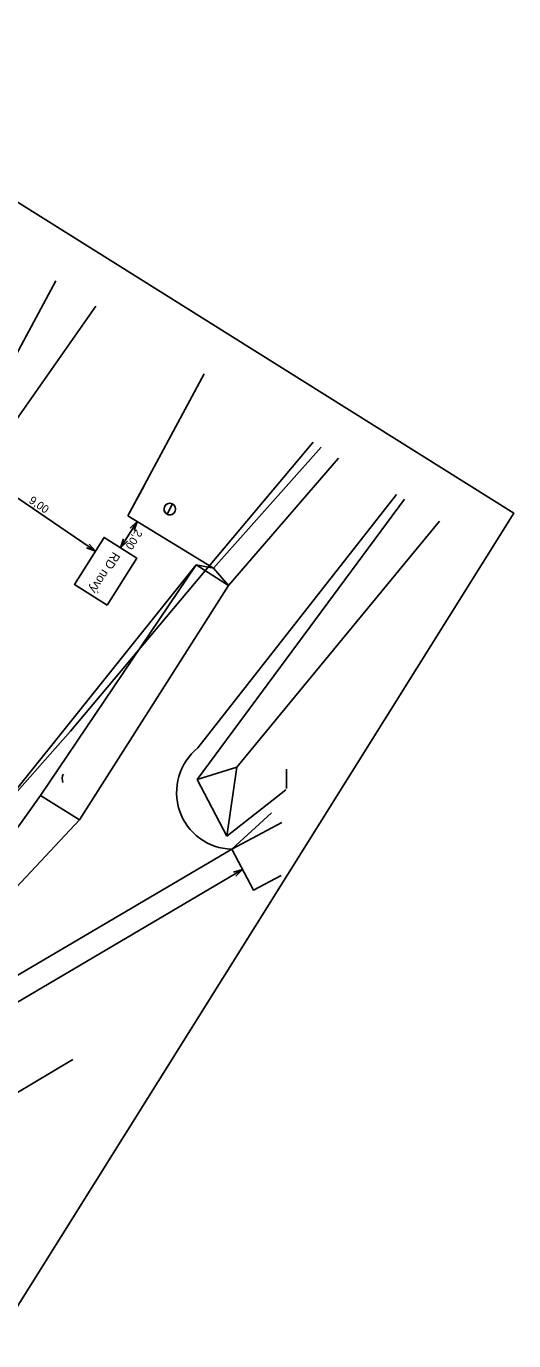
# Model space of a CAD drawing. Extents: x -794960 to -794828, y -1135115 to -1134953.
# Drawn here: x -794859.2 to -794827.6, y -1135038 to -1134952.8 of the extents above; entities that cross this region are included whole.
import ezdxf

# ---------------------------------------------------------------- set-up
doc = ezdxf.new("R2010")
doc.units = 0
for name, color, linetype in [('Implicitní', 7, 'Continuous'), ('Schéma', 7, 'Continuous'), ('Stsitu', 7, 'Continuous'), ('Stsitu - koleje', 7, 'Continuous'), ('Vrstva 1', 7, 'Continuous'), ('Vzor', 7, 'Continuous')]:
    doc.layers.add(name, color=color, linetype=linetype)

msp = doc.modelspace()

# ---------------------------------------------------------------- linework, layer by layer
at = {"layer": 'Implicitní'}
for p, q in [((-794862.154, -1134981.748), (-794854.692, -1134986.84)), ((-794851.996, -1134984.913), (-794853.067, -1134986.616)), ((-794871.111, -1135022.7), (-794845.154, -1135007.46))]:
    msp.add_line(p, q, dxfattribs=at)
for points in [[(-794852.188, -1134985.5), (-794851.996, -1134984.913), (-794852.442, -1134985.341)], [(-794852.875, -1134986.028), (-794853.067, -1134986.616), (-794852.621, -1134986.188)], [(-794855.272, -1134986.625), (-794854.692, -1134986.84), (-794855.103, -1134986.378)], [(-794845.597, -1135007.891), (-794845.154, -1135007.46), (-794845.748, -1135007.632)]]:
    msp.add_lwpolyline(points, dxfattribs=at)
at = {"layer": 'Schéma'}
msp.add_lwpolyline([(-794853.925, -1134990.329), (-794852.009, -1134987.281), (-794854.125, -1134985.95), (-794856.042, -1134988.998)], close=True, dxfattribs=at)
at = {"layer": 'Stsitu'}
for p, q in [((-794852.583, -1134984.556), (-794847.643, -1134975.356)), ((-794840.58, -1134979.778), (-794856.3, -1134998.501)), ((-794840.057, -1134980.106), (-794847.031, -1134987.928)), ((-794838.933, -1134980.809), (-794846.073, -1134989.059)), ((-794852.583, -1134984.556), (-794851.532, -1134982.599)), ((-794834.673, -1134983.477), (-794848.099, -1135001.612)), ((-794835.182, -1134983.158), (-794848.049, -1134999.571)), ((-794849.694, -1134983.778), (-794850.05, -1134984.44)), ((-794849.777, -1134983.933), (-794850.05, -1134984.44)), ((-794847.031, -1134987.928), (-794852.583, -1134984.556)), ((-794832.404, -1134984.898), (-794845.522, -1135000.83)), ((-794863.119, -1135006.371), (-794848.162, -1134987.718)), ((-794848.162, -1134987.718), (-794858.241, -1135002.662)), ((-794846.073, -1134989.059), (-794848.162, -1134987.718)), ((-794848.162, -1134987.718), (-794847.031, -1134987.928)), ((-794847.031, -1134987.928), (-794846.073, -1134989.059)), ((-794846.073, -1134989.059), (-794855.733, -1135004.243)), ((-794856.3, -1134998.501), (-794867.635, -1135011.242)), ((-794856.849, -1135001.563), (-794856.822, -1135001.353)), ((-794856.822, -1135001.353), (-794856.769, -1135001.275)), ((-794845.522, -1135000.83), (-794848.099, -1135001.612)), ((-794845.522, -1135000.83), (-794846.173, -1135005.288)), ((-794856.798, -1135001.825), (-794856.849, -1135001.563)), ((-794848.099, -1135001.612), (-794846.173, -1135005.288)), ((-794858.241, -1135002.662), (-794861.943, -1135007.826)), ((-794858.241, -1135002.662), (-794855.733, -1135004.243)), ((-794846.173, -1135005.288), (-794842.351, -1135002.29)), ((-794845.859, -1135006.134), (-794843.287, -1135003.786)), ((-794855.733, -1135004.243), (-794871.739, -1135021.338)), ((-794871.739, -1135021.338), (-794845.859, -1135006.134)), ((-794873.355, -1135030.02), (-794856.162, -1135019.751))]:
    msp.add_line(p, q, dxfattribs=at)
msp.add_circle((-794849.872, -1134984.109), 0.376, dxfattribs=at)
msp.add_arc((-794849.872, -1134984.109), 0.376, 115.9563, 359.94219, dxfattribs=at)
msp.add_ellipse((-794845.742, -1135002.436), major_axis=(-2.169, -3.012), ratio=0.990529, start_param=4.446216, end_param=6.879975, dxfattribs=at)
at = {"layer": 'Stsitu - koleje'}
for p, q in [((-794857.25, -1134969.341), (-794861.916, -1134977.994)), ((-794854.661, -1134970.962), (-794860.098, -1134978.738))]:
    msp.add_line(p, q, dxfattribs=at)
at = {"layer": 'Vrstva 1'}
msp.add_line((-794842.303, -1135000.953), (-794842.303, -1135002.213), dxfattribs=at)
msp.add_lwpolyline([(-794909.184, -1135114.688), (-794827.592, -1134984.371), (-794877.938, -1134952.849), (-794959.53, -1135083.166)], close=True, dxfattribs=at)
msp.add_lwpolyline([(-794842.652, -1135007.827), (-794844.451, -1135008.783), (-794845.859, -1135006.134), (-794842.61, -1135004.407)], dxfattribs=at)

# ---------------------------------------------------------------- texts
at = {"layer": 'Schéma'}
msp.add_text('RD nový', height=0.576, rotation=237.83602, dxfattribs=at).set_placement((-794853.536, -1134986.838))
at = {"layer": 'Vzor'}
for s, rotation, p in [('9,00', 325.694, (-794859.045, -1134983.663)), ('2,00', 237.83601, (-794852.048, -1134985.382))]:
    msp.add_text(s, height=0.5184, rotation=rotation, dxfattribs=at).set_placement(p)

doc.saveas('drawing.dxf')
